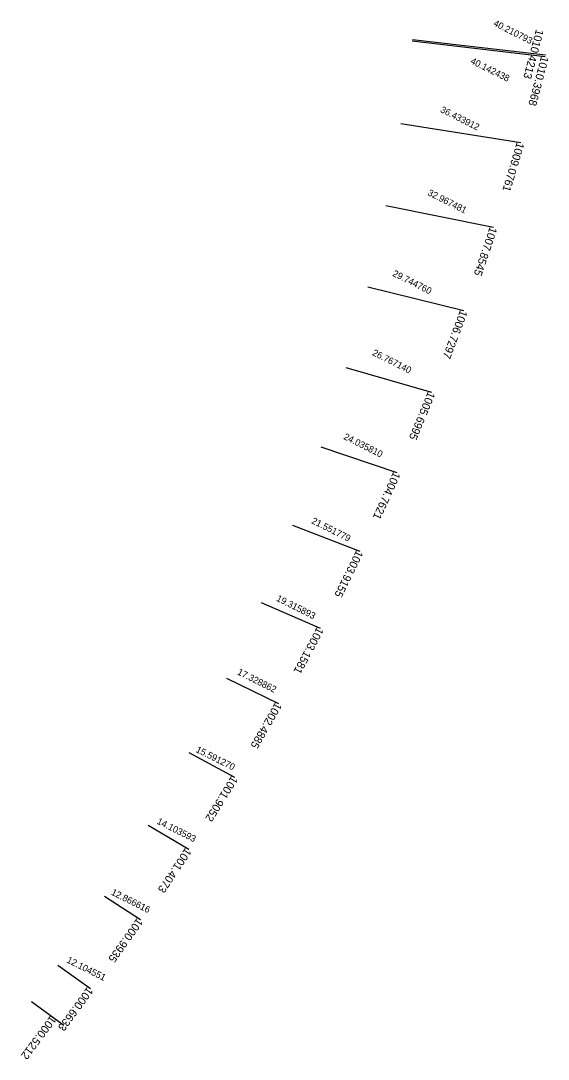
# Model space of a CAD drawing. Extents: x 1608399 to 16975600, y 1093178 to 12565486.
# Drawn here: x 1609583.9 to 1609742.2, y 1093178 to 1093489.4 of the extents above; entities that cross this region are included whole.
import ezdxf

# ---------------------------------------------------------------- set-up
doc = ezdxf.new("R2010")
doc.units = 0
for name, color, linetype in [('Default', 7, 'Continuous'), ('RD_PD_Supershp_Ramp_2', 7, 'Continuous'), ('RD_Sketch1', 7, 'Continuous')]:
    doc.layers.add(name, color=color, linetype=linetype)

msp = doc.modelspace()

# ---------------------------------------------------------------- linework, layer by layer
at = {"layer": 'RD_Sketch1'}
for p, q in [((1609741.23, 1093478.65), (1609701.36, 1093483.31)), ((1609741.35, 1093479.12), (1609701.41, 1093483.76)), ((1609733.92, 1093452.81), (1609697.94, 1093458.55)), ((1609725.8, 1093427.41), (1609693.49, 1093433.95)), ((1609716.9, 1093402.45), (1609688.02, 1093409.56)), ((1609707.24, 1093377.94), (1609681.54, 1093385.41)), ((1609696.84, 1093353.89), (1609674.06, 1093361.56)), ((1609685.71, 1093330.32), (1609665.59, 1093338.04)), ((1609673.88, 1093307.23), (1609656.15, 1093314.89)), ((1609661.36, 1093284.63), (1609645.76, 1093292.16)), ((1609648.17, 1093262.52), (1609634.42, 1093269.88)), ((1609634.32, 1093240.92), (1609622.17, 1093248.09)), ((1609619.82, 1093219.83), (1609609.02, 1093226.83)), ((1609604.88, 1093199.14), (1609595, 1093206.13)), ((1609587.18, 1093195.36), (1609596.82, 1093188.21))]:
    msp.add_line(p, q, dxfattribs=at)

# ---------------------------------------------------------------- texts
at = {"layer": 'Default'}
for s, rotation, p in [('1010.4213', 255.1959, (1609738.55, 1093487.06)), ('1010.3968', 255.1615, (1609740.07, 1093478.96)), ('1009.0761', 253.2384, (1609732.77, 1093453.16)), ('1007.8545', 251.3282, (1609724.67, 1093427.79)), ('1006.7297', 249.4301, (1609715.78, 1093402.87)), ('1005.6995', 247.5432, (1609706.13, 1093378.4)), ('1004.7621', 245.6668, (1609695.75, 1093354.39)), ('1003.9155', 243.7998, (1609684.64, 1093330.85)), ('1003.1581', 241.9415, (1609672.82, 1093307.79)), ('1002.4885', 240.0909, (1609660.32, 1093285.23)), ('1001.9052', 238.2471, (1609647.15, 1093263.15)), ('1001.4073', 236.4093, (1609633.32, 1093241.59)), ('1000.9935', 234.5765, (1609618.84, 1093220.53)), ('1000.6633', 233.8007, (1609603.91, 1093199.85)), ('1000.5212', 233.4116, (1609592.87, 1093191.3))]:
    msp.add_text(s, height=2.4, rotation=rotation, dxfattribs=at).set_placement(p)
at = {"layer": 'RD_PD_Supershp_Ramp_2'}
for s, p in [('40.210793', (1609725.53, 1093488.06)), ('40.142438', (1609718.66, 1093476.76)), ('36.433912', (1609709.61, 1093462.15)), ('32.967481', (1609705.81, 1093437.24)), ('29.744760', (1609695.29, 1093413.02)), ('26.767140', (1609689.2, 1093389.26)), ('24.035810', (1609680.6, 1093364.08)), ('21.551779', (1609670.96, 1093338.84)), ('19.315893', (1609660.42, 1093315.59)), ('17.328862', (1609648.69, 1093293.51)), ('15.591270', (1609636.26, 1093270.25)), ('14.103593', (1609624.57, 1093248.73)), ('12.866616', (1609610.85, 1093227.46)), ('12.104551', (1609597.52, 1093207.14))]:
    msp.add_text(s, height=2, rotation=333.3522, dxfattribs=at).set_placement(p)

doc.saveas('drawing.dxf')
